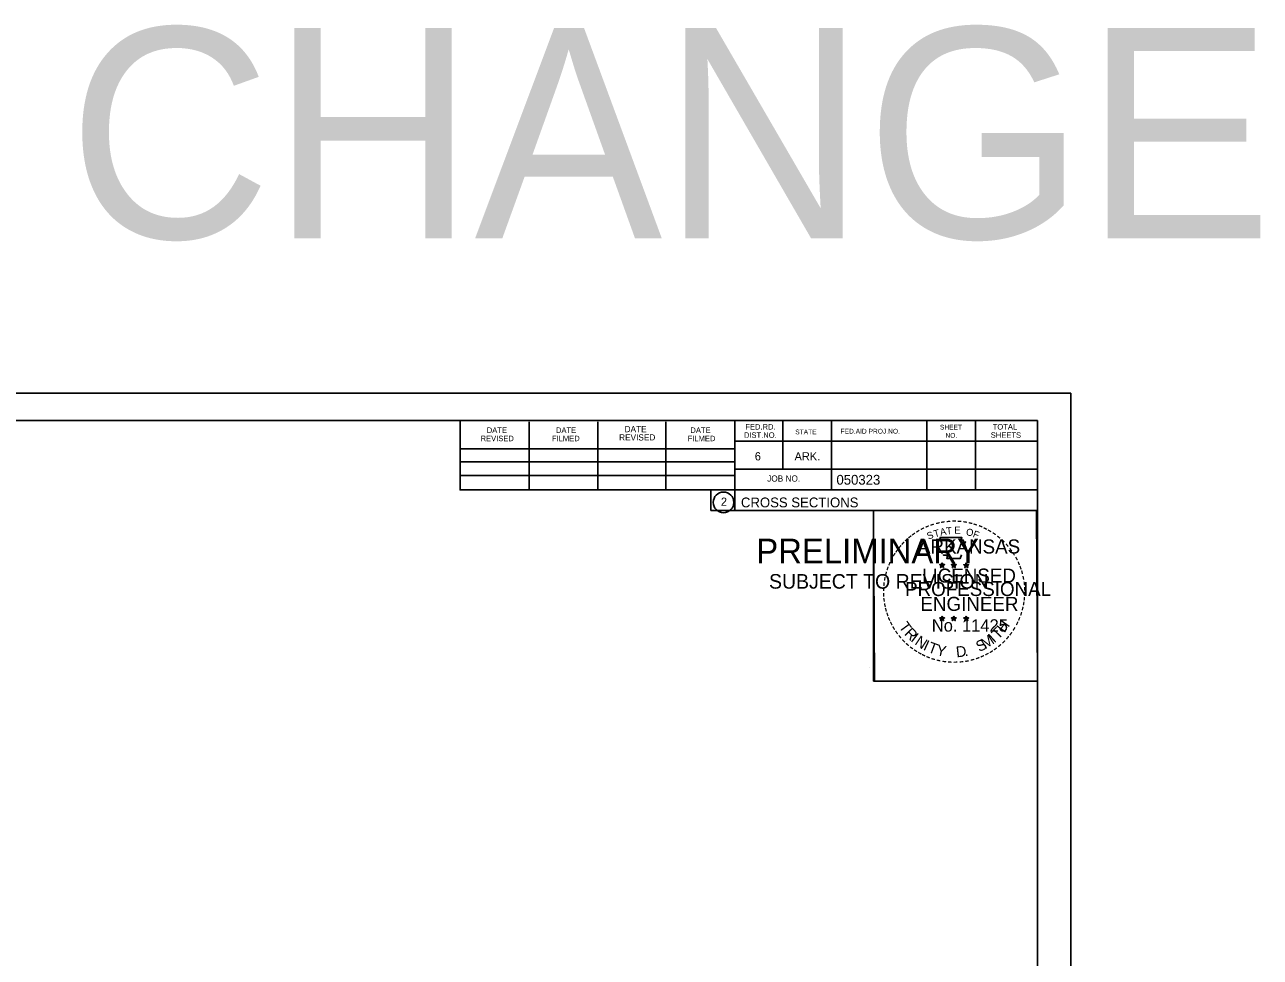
# Model space of a CAD drawing. Extents: x 1360146 to 1361431, y 631444 to 632352.
# Drawn here: x 1361254.5 to 1361430.6, y 632057 to 632190 of the extents above; entities that cross this region are included whole.
import ezdxf

# ---------------------------------------------------------------- set-up
doc = ezdxf.new("R2010")
doc.units = 0
for name, color, linetype in [('Default', 7, 'Continuous'), ('R_Border', 7, 'Continuous'), ('R_Border PE', 7, 'Continuous'), ('R_Border Prem', 7, 'Continuous'), ('R_No Plot', 7, 'Continuous')]:
    doc.layers.add(name, color=color, linetype=linetype)

msp = doc.modelspace()

# ---------------------------------------------------------------- linework, layer by layer
at = {"layer": 'R_Border'}
for p, q in [((1361082.6, 632133.55), (1361398.78, 632133.55)), ((1361316.52, 632123.67), (1361316.52, 632133.55)), ((1361326.38, 632123.67), (1361326.38, 632133.35)), ((1361336.14, 632123.67), (1361336.14, 632133.35)), ((1361345.82, 632123.67), (1361345.82, 632133.35)), ((1361355.68, 632133.55), (1361355.68, 632120.75)), ((1361362.52, 632133.55), (1361362.52, 632126.61)), ((1361369.46, 632133.55), (1361369.46, 632123.67)), ((1361383.04, 632133.55), (1361383.04, 632123.67)), ((1361389.98, 632133.55), (1361389.98, 632123.67)), ((1361398.78, 631928.09), (1361398.78, 632133.55)), ((1361316.52, 632129.53), (1361355.68, 632129.53)), ((1361398.78, 632130.61), (1361355.68, 632130.61)), ((1361398.78, 632130.63), (1361398.78, 632130.63)), ((1361316.52, 632127.67), (1361355.68, 632127.67)), ((1361316.52, 632123.67), (1361316.52, 632125.73)), ((1361316.52, 632125.73), (1361355.68, 632125.73)), ((1361398.78, 632126.61), (1361355.68, 632126.61)), ((1361358.64, 632126.61), (1361398.78, 632126.61)), ((1361398.78, 632123.67), (1361316.52, 632123.67)), ((1361355.68, 632120.75), (1361398.78, 632120.75))]:
    msp.add_line(p, q, dxfattribs=at)
msp.add_circle((1361354.06, 632121.89), 1.47, dxfattribs=at)
at = {"layer": 'R_Border PE'}
for p, q in [((1361385.21, 632113.26), (1361385.17, 632113.01)), ((1361385.21, 632112.9), (1361385.21, 632113.26)), ((1361385.21, 632113.26), (1361385.26, 632113.01)), ((1361386.88, 632113.26), (1361386.84, 632113.01)), ((1361386.88, 632112.9), (1361386.88, 632113.26)), ((1361386.88, 632113.26), (1361386.93, 632113.01)), ((1361388.65, 632113.25), (1361388.6, 632113)), ((1361388.65, 632112.88), (1361388.65, 632113.25)), ((1361388.65, 632113.25), (1361388.69, 632113)), ((1361384.86, 632113.01), (1361385.21, 632112.9)), ((1361384.86, 632113.01), (1361385.12, 632112.96)), ((1361384.86, 632113.01), (1361385.1, 632112.88)), ((1361385, 632112.6), (1361385.21, 632112.9)), ((1361385, 632112.6), (1361385.12, 632112.84)), ((1361385, 632112.6), (1361385.21, 632112.82)), ((1361385.56, 632113.01), (1361385.21, 632112.9)), ((1361385.42, 632112.6), (1361385.21, 632112.9)), ((1361385.42, 632112.6), (1361385.21, 632112.81)), ((1361385.56, 632113.01), (1361385.27, 632112.96)), ((1361385.42, 632112.6), (1361385.29, 632112.89)), ((1361385.56, 632113.01), (1361385.35, 632112.9)), ((1361386.53, 632113.01), (1361386.88, 632112.9)), ((1361386.53, 632113.01), (1361386.79, 632112.96)), ((1361386.53, 632113.01), (1361386.77, 632112.88)), ((1361386.67, 632112.6), (1361386.88, 632112.9)), ((1361386.67, 632112.6), (1361386.79, 632112.84)), ((1361386.67, 632112.6), (1361386.88, 632112.82)), ((1361387.23, 632113.01), (1361386.88, 632112.9)), ((1361387.09, 632112.6), (1361386.88, 632112.9)), ((1361387.09, 632112.6), (1361386.88, 632112.81)), ((1361387.23, 632113.01), (1361386.94, 632112.96)), ((1361387.09, 632112.6), (1361386.96, 632112.89)), ((1361387.23, 632113.01), (1361387.02, 632112.9)), ((1361388.3, 632112.99), (1361388.65, 632112.88)), ((1361388.3, 632112.99), (1361388.55, 632112.95)), ((1361388.3, 632112.99), (1361388.53, 632112.87)), ((1361388.43, 632112.59), (1361388.65, 632112.88)), ((1361388.43, 632112.59), (1361388.56, 632112.83)), ((1361388.43, 632112.59), (1361388.64, 632112.8)), ((1361388.86, 632112.59), (1361388.64, 632112.8)), ((1361388.99, 632112.99), (1361388.65, 632112.88)), ((1361388.86, 632112.59), (1361388.65, 632112.88)), ((1361388.99, 632112.99), (1361388.71, 632112.95)), ((1361388.86, 632112.59), (1361388.72, 632112.88)), ((1361388.99, 632112.99), (1361388.79, 632112.89)), ((1361384.86, 632105.43), (1361385.21, 632105.32)), ((1361384.86, 632105.43), (1361385.11, 632105.39)), ((1361384.86, 632105.43), (1361385.1, 632105.31)), ((1361384.99, 632105.03), (1361385.21, 632105.32)), ((1361384.99, 632105.03), (1361385.12, 632105.27)), ((1361384.99, 632105.03), (1361385.21, 632105.24)), ((1361385.21, 632105.69), (1361385.17, 632105.44)), ((1361385.21, 632105.32), (1361385.21, 632105.69)), ((1361385.21, 632105.69), (1361385.26, 632105.44)), ((1361385.55, 632105.43), (1361385.21, 632105.32)), ((1361385.42, 632105.03), (1361385.21, 632105.32)), ((1361385.42, 632105.03), (1361385.21, 632105.24)), ((1361385.55, 632105.43), (1361385.27, 632105.38)), ((1361385.42, 632105.03), (1361385.28, 632105.32)), ((1361385.55, 632105.43), (1361385.35, 632105.33)), ((1361386.53, 632105.43), (1361386.88, 632105.32)), ((1361386.53, 632105.43), (1361386.78, 632105.39)), ((1361386.53, 632105.43), (1361386.76, 632105.31)), ((1361386.66, 632105.03), (1361386.88, 632105.32)), ((1361386.66, 632105.03), (1361386.79, 632105.27)), ((1361386.66, 632105.03), (1361386.87, 632105.24)), ((1361386.88, 632105.69), (1361386.84, 632105.44)), ((1361387.09, 632105.03), (1361386.87, 632105.24)), ((1361386.88, 632105.32), (1361386.88, 632105.69)), ((1361386.88, 632105.69), (1361386.93, 632105.44)), ((1361387.22, 632105.43), (1361386.88, 632105.32)), ((1361387.09, 632105.03), (1361386.88, 632105.32)), ((1361387.22, 632105.43), (1361386.94, 632105.38)), ((1361387.09, 632105.03), (1361386.95, 632105.32)), ((1361387.22, 632105.43), (1361387.02, 632105.33)), ((1361388.29, 632105.42), (1361388.64, 632105.31)), ((1361388.29, 632105.42), (1361388.55, 632105.38)), ((1361388.29, 632105.42), (1361388.53, 632105.3)), ((1361388.43, 632105.02), (1361388.64, 632105.31)), ((1361388.43, 632105.02), (1361388.55, 632105.26)), ((1361388.43, 632105.02), (1361388.64, 632105.23)), ((1361388.64, 632105.68), (1361388.6, 632105.43)), ((1361388.64, 632105.31), (1361388.64, 632105.68)), ((1361388.64, 632105.68), (1361388.69, 632105.43)), ((1361388.99, 632105.42), (1361388.64, 632105.31)), ((1361388.86, 632105.02), (1361388.64, 632105.31)), ((1361388.86, 632105.02), (1361388.64, 632105.23)), ((1361388.99, 632105.42), (1361388.7, 632105.37)), ((1361388.86, 632105.02), (1361388.72, 632105.31)), ((1361388.99, 632105.42), (1361388.79, 632105.32))]:
    msp.add_line(p, q, dxfattribs=at)
for points in [[(1361384.9, 632116.88), (1361385.17, 632116.06)], [(1361388.41, 632115.96), (1361388.56, 632116.25), (1361387.87, 632116.22), (1361388.02, 632116.88), (1361384.9, 632116.88)], [(1361385.21, 632113.26), (1361385.42, 632112.6), (1361384.86, 632113.01), (1361385.56, 632113.01), (1361385, 632112.6), (1361385.21, 632113.26)], [(1361385.4, 632114.46), (1361385.4, 632114.37), (1361385.96, 632114.36), (1361385.9, 632113.88), (1361387.77, 632113.88), (1361387.98, 632114.42)], [(1361386.88, 632113.26), (1361387.09, 632112.6), (1361386.53, 632113.01), (1361387.23, 632113.01), (1361386.67, 632112.6), (1361386.88, 632113.26)], [(1361388.65, 632113.25), (1361388.86, 632112.59), (1361388.3, 632112.99), (1361388.99, 632112.99), (1361388.43, 632112.59), (1361388.65, 632113.25)], [(1361385.21, 632105.69), (1361385.42, 632105.03), (1361384.86, 632105.43), (1361385.55, 632105.43), (1361384.99, 632105.03), (1361385.21, 632105.69)], [(1361386.88, 632105.69), (1361387.09, 632105.03), (1361386.53, 632105.43), (1361387.22, 632105.43), (1361386.66, 632105.03), (1361386.88, 632105.69)], [(1361388.64, 632105.68), (1361388.86, 632105.02), (1361388.29, 632105.42), (1361388.99, 632105.42), (1361388.43, 632105.02), (1361388.64, 632105.68)]]:
    msp.add_lwpolyline(points, dxfattribs=at)
for centre, radius in [((1361385.21, 632112.89), 0.172), ((1361385.21, 632112.89), 0.145), ((1361385.21, 632112.89), 0.116), ((1361385.21, 632112.89), 0.0991), ((1361385.21, 632112.89), 0.0747), ((1361385.21, 632112.89), 0.0495), ((1361385.21, 632112.89), 0.0296), ((1361386.88, 632112.89), 0.172), ((1361386.88, 632112.89), 0.145), ((1361386.88, 632112.89), 0.116), ((1361386.88, 632112.89), 0.0991), ((1361386.88, 632112.89), 0.0747), ((1361386.88, 632112.89), 0.0495), ((1361386.88, 632112.89), 0.0296), ((1361388.64, 632112.88), 0.172), ((1361388.64, 632112.88), 0.145), ((1361388.64, 632112.88), 0.116), ((1361388.64, 632112.88), 0.0991), ((1361388.64, 632112.88), 0.0747), ((1361388.64, 632112.88), 0.0495), ((1361388.64, 632112.88), 0.0296), ((1361385.21, 632105.32), 0.172), ((1361385.21, 632105.32), 0.145), ((1361385.21, 632105.32), 0.116), ((1361385.21, 632105.32), 0.0991), ((1361385.21, 632105.32), 0.0747), ((1361385.21, 632105.32), 0.0495), ((1361385.21, 632105.32), 0.0296), ((1361386.88, 632105.32), 0.172), ((1361386.88, 632105.32), 0.145), ((1361386.88, 632105.32), 0.116), ((1361386.88, 632105.32), 0.0991), ((1361386.88, 632105.32), 0.0747), ((1361386.88, 632105.32), 0.0495), ((1361386.88, 632105.32), 0.0296), ((1361388.64, 632105.31), 0.172), ((1361388.64, 632105.31), 0.145), ((1361388.64, 632105.31), 0.116), ((1361388.64, 632105.31), 0.0991), ((1361388.64, 632105.31), 0.0747), ((1361388.64, 632105.31), 0.0495), ((1361388.64, 632105.31), 0.0296)]:
    msp.add_circle(centre, radius, dxfattribs=at)
at = {"layer": 'R_No Plot'}
for p, q in [((1361070.2, 632137.45), (1361403.53, 632137.45)), ((1361374.81, 632098.3), (1361374.81, 632098.3))]:
    msp.add_line(p, q, dxfattribs=at)
for points in [[(1361070.19, 632137.45), (1361403.53, 632137.45), (1361403.53, 631924.11), (1361070.19, 631924.11)], [(1361316.52, 632133.55), (1361316.52, 632123.67), (1361352.25, 632123.67), (1361352.25, 632120.75), (1361375.45, 632120.75), (1361375.45, 632096.42), (1361398.78, 632096.42), (1361398.78, 631928.09), (1361082.6, 631928.09), (1361082.6, 632133.55)], [(1361375.45, 632120.75), (1361398.66, 632120.75), (1361398.78, 632096.42), (1361375.57, 632096.42)]]:
    msp.add_lwpolyline(points, close=True, dxfattribs=at)

# ---------------------------------------------------------------- texts
at = {"layer": 'Default'}
msp.add_text('CHANNEL CHANGE', height=30, dxfattribs=at).set_placement((1361057.78, 632159.53))
at = {"layer": 'R_Border'}
for s, height, p in [('DATE', 0.879, (1361339.96, 632131.89)), ('FED.RD.', 0.782, (1361357.16, 632132.27)), ('SHEET', 0.684, (1361384.9, 632132.27)), ('TOTAL', 0.782, (1361392.42, 632132.27)), ('REVISED', 0.782, (1361319.44, 632130.61)), ('DATE', 0.782, (1361320.32, 632131.79)), ('FILMED', 0.782, (1361329.6, 632130.61)), ('DATE', 0.782, (1361330.18, 632131.79)), ('REVISED', 0.879, (1361339.18, 632130.71)), ('FILMED', 0.782, (1361348.94, 632130.61)), ('DATE', 0.782, (1361349.34, 632131.79)), ('DIST.NO.', 0.782, (1361356.96, 632131.09)), ('STATE', 0.684, (1361364.28, 632131.59)), ('FED.AID PROJ.NO.', 0.684, (1361370.74, 632131.69)), ('NO.', 0.684, (1361385.68, 632131.09)), ('SHEETS', 0.782, (1361392.14, 632131.09)), ('6', 1.17, (1361358.52, 632127.87)), ('ARK.', 1.172, (1361364.18, 632127.87)), ('JOB NO.', 0.879, (1361360.28, 632124.85)), ('050323', 1.4, (1361370.15, 632124.41)), ('2', 1.17, (1361353.68, 632121.4)), ('CROSS SECTIONS', 1.4, (1361356.54, 632121.18))]:
    msp.add_text(s, height=height, rotation=360, dxfattribs=at).set_placement(p)
at = {"layer": 'R_Border PE'}
for s, height, rotation, p in [('-', 1.6, 24.3072, (1361383.02, 632117.74)), ('-', 1.6, 19.1761, (1361383.65, 632118.01)), ('-', 1.6, 13.6301, (1361384.4, 632118.25)), ('-', 1.6, 10.2193, (1361385.08, 632118.41)), ('-', 1.6, 5.8968, (1361385.81, 632118.52)), ('-', 1.6, 0.1862, (1361386.58, 632118.6)), ('-', 1.6, 357.743, (1361387.3, 632118.58)), ('-', 1.6, 352.1617, (1361388.05, 632118.53)), ('-', 1.6, 347.2049, (1361388.77, 632118.41)), ('-', 1.6, 342.3362, (1361389.4, 632118.26)), ('-', 1.6, 337.8551, (1361390.14, 632118.04)), ('-', 1.6, 42.9622, (1361380.3, 632115.87)), ('-', 1.6, 38.9507, (1361380.73, 632116.28)), ('-', 1.6, 36.2317, (1361381.21, 632116.66)), ('-', 1.6, 34.0636, (1361381.79, 632117.06)), ('-', 1.6, 28.7918, (1361382.38, 632117.43)), ('S', 1, 21.594, (1361383.26, 632116.56)), ('T', 1, 16.4036, (1361384.17, 632116.89)), ('A', 1, 11.2132, (1361385, 632117.14)), ('T', 1, 6.0228, (1361385.85, 632117.31)), ('E', 1, 0.8323, (1361386.95, 632117.42)), ('O', 1, 350.4515, (1361388.56, 632117.21)), ('F', 1, 340.0707, (1361389.51, 632116.98)), ('-', 1.6, 334.1211, (1361390.77, 632117.76)), ('-', 1.6, 329.6409, (1361391.35, 632117.48)), ('-', 1.6, 325.8627, (1361391.99, 632117.12)), ('-', 1.6, 320.5297, (1361392.6, 632116.69)), ('-', 1.6, 54.2325, (1361379.04, 632114.33)), ('-', 1.6, 50.6142, (1361379.45, 632114.9)), ('-', 1.6, 48.423, (1361379.85, 632115.39)), ('ARKANSAS', 2, 360, (1361381.76, 632114.6)), ('-', 1.6, 315.5786, (1361393.2, 632116.21)), ('-', 1.6, 309.8797, (1361393.77, 632115.66)), ('-', 1.6, 306.6522, (1361394.29, 632115.05)), ('-', 1.6, 67.7743, (1361378.14, 632112.58)), ('-', 1.6, 62.8713, (1361378.4, 632113.19)), ('-', 1.6, 58.0706, (1361378.71, 632113.81)), ('-', 1.4, 303.6753, (1361394.78, 632114.49)), ('-', 1.6, 299.6684, (1361395.1, 632113.88)), ('-', 1.6, 294.6628, (1361395.42, 632113.27)), ('-', 1.6, 75.461, (1361377.72, 632111.24)), ('-', 1.6, 72.3945, (1361377.92, 632111.95)), ('LICENSED', 2, 360, (1361382.35, 632110.45)), ('DWB', 0.01, 360, (1361385.2, 632112.89)), ('DWB', 0.01, 360, (1361386.87, 632112.89)), ('DWB', 0.01, 360, (1361388.63, 632112.88)), ('-', 1.6, 290.5728, (1361395.68, 632112.69)), ('-', 1.6, 285.1233, (1361395.91, 632112.11)), ('-', 1.6, 89.0622, (1361377.49, 632109.13)), ('-', 1.6, 85.1863, (1361377.51, 632109.83)), ('-', 1.6, 81.2013, (1361377.59, 632110.53)), ('PROFESSIONAL', 2, 360, (1361379.93, 632108.54)), ('-', 1.6, 280.5493, (1361396.11, 632111.37)), ('-', 1.6, 276.5962, (1361396.27, 632110.6)), ('-', 1.6, 274.3301, (1361396.33, 632109.88)), ('-', 1.6, 94.1959, (1361377.52, 632108.41)), ('-', 1.6, 98.9479, (1361377.6, 632107.74)), ('ENGINEER', 2, 360, (1361382.12, 632106.42)), ('-', 1.6, 263.5172, (1361396.35, 632108.58)), ('-', 1.6, 269.9407, (1361396.37, 632109.25)), ('-', 1.6, 101.7149, (1361377.73, 632107.01)), ('-', 1.6, 105.4578, (1361377.89, 632106.41)), ('-', 1.6, 109.0874, (1361378.11, 632105.78)), ('-', 1.6, 252.8681, (1361395.99, 632106.53)), ('-', 1.6, 255.7626, (1361396.17, 632107.25)), ('-', 1.6, 260.9953, (1361396.28, 632107.93)), ('-', 1.6, 114.0643, (1361378.36, 632105.19)), ('-', 1.6, 115.7289, (1361378.67, 632104.57)), ('T', 1.54, 306.0406, (1361378.97, 632104.16)), ('No. 11425', 1.757, 360, (1361383.74, 632103.47)), ('DWB', 0.01, 360, (1361385.19, 632105.32)), ('DWB', 0.01, 360, (1361386.86, 632105.32)), ('DWB', 0.01, 360, (1361388.63, 632105.31)), ('H', 1.54, 54.6088, (1361394.09, 632103.2)), ('-', 1.6, 244.6197, (1361395.5, 632105.23)), ('-', 1.6, 247.8887, (1361395.76, 632105.86)), ('-', 1.6, 120.4471, (1361379.02, 632103.98)), ('-', 1.6, 125.8934, (1361379.43, 632103.42)), ('-', 1.6, 130.7181, (1361379.89, 632102.87)), ('R', 1.54, 314.005, (1361379.73, 632103.11)), ('I', 1.54, 321.9694, (1361380.63, 632102.18)), ('N', 1.54, 326.5002, (1361381.2, 632101.71)), ('M', 1.54, 32.6563, (1361391.35, 632100.93)), ('I', 1.54, 42.1136, (1361392.64, 632101.77)), ('T', 1.54, 46.6444, (1361393.2, 632102.25)), ('-', 1.6, 231.2538, (1361394.28, 632103.26)), ('-', 1.6, 233.8452, (1361394.71, 632103.82)), ('-', 1.6, 239.0712, (1361395.11, 632104.47)), ('-', 1.6, 134.2238, (1361380.41, 632102.32)), ('-', 1.6, 138.9338, (1361380.93, 632101.86)), ('-', 1.6, 144.6463, (1361381.49, 632101.45)), ('-', 1.6, 148.0898, (1361382.05, 632101.08)), ('I', 1.54, 335.3603, (1361382.41, 632100.92)), ('T', 1.54, 339.8912, (1361383.07, 632100.6)), ('Y', 1.54, 347.8556, (1361384.28, 632100.15)), ('D', 1.54, 6.3969, (1361387.27, 632099.79)), ('S', 1.54, 26.9312, (1361390.51, 632100.52)), ('-', 1.6, 215.7363, (1361392.73, 632101.71)), ('-', 1.6, 221.0851, (1361393.27, 632102.18)), ('-', 1.6, 225.7653, (1361393.8, 632102.69)), ('-', 1.6, 151.5704, (1361382.63, 632100.76)), ('-', 1.6, 154.6002, (1361383.15, 632100.51)), ('-', 1.6, 158.5612, (1361383.77, 632100.26)), ('-', 1.6, 162.7983, (1361384.46, 632100.04)), ('-', 1.6, 167.5555, (1361385.18, 632099.88)), ('-', 1.6, 173.1155, (1361385.95, 632099.77)), ('-', 1.6, 176.5183, (1361386.7, 632099.72)), ('-', 1.6, 181.5918, (1361387.44, 632099.74)), ('-', 1.6, 185.8167, (1361388.25, 632099.81)), ('-', 1.6, 191.2858, (1361388.98, 632099.94)), ('.', 1.54, 13.7642, (1361388.46, 632099.92)), ('-', 1.6, 195.4743, (1361389.71, 632100.14)), ('-', 1.6, 200.7184, (1361390.39, 632100.39)), ('-', 1.6, 204.2516, (1361391.01, 632100.66)), ('-', 1.6, 207.3568, (1361391.63, 632100.98)), ('-', 1.6, 212.2491, (1361392.19, 632101.32))]:
    msp.add_text(s, height=height, rotation=rotation, dxfattribs=at).set_placement(p)
at = {"layer": 'R_Border Prem'}
for s, height, p in [('PRELIMINARY', 3.5, (1361358.73, 632113.21)), ('DWB', 0.01, (1361359.47, 632115.06)), ('SUBJECT TO REVISION', 2.0751, (1361360.54, 632109.59))]:
    msp.add_text(s, height=height, rotation=360, dxfattribs=at).set_placement(p)

doc.saveas('drawing.dxf')
